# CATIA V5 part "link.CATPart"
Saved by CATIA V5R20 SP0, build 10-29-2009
Part number: link
Bounding box of the stored display mesh (mm): x -25 to 25, y -12.5 to 12.5, z -9.5 to 9.5
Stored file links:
  D:\Documents and Settings\mosavian\My Documents\DMU Project3\New Folder\link.CATPart
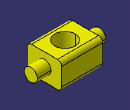
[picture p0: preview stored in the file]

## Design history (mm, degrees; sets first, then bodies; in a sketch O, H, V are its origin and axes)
Body1 (main body)
  Sketch1 on yz-plane, origin (0, 0, 0), H (0, 1, 0), V (0, 0, 1)
    circle A1 centre (0, 0) radius 4.75
    radius A1 = 4.75
  Pad1: profile Sketch1, direction (1, 0, 0), length 25, mirrored extent
  Sketch2 on yz-plane, origin (0, 0, 0), H (0, 1, 0), V (0, 0, 1)
    line L1 (12.5, 9.5) -> (12.5, -9.5)
    line L2 (12.5, -9.5) -> (-12.5, -9.5)
    line L3 (-12.5, -9.5) -> (-12.5, 9.5)
    line L4 (-12.5, 9.5) -> (12.5, 9.5)
    length L4 = 25
    length L1 = 19
    vertical: L1 V, L3 V
    horizontal: L2 H, L4 H
    equidistance: L1 L3 O, L2 L4 O
  Pad2: profile Sketch2, direction (1, 0, 0), length 15, mirrored extent
  Sketch3 on face of Pad2 from Sketch2.L4, origin (0, 0, 9.5), H (1, 0, 0), V (0, 1, 0)
    circle A1 centre (0, 0) radius 7.5
    radius A1 = 7.5
  Pocket1: profile Sketch3, direction (0, 0, -1), through (limit type 6)
  Fillet1: radius 3, on edge [face of Pad2 from Sketch2.L4 | face of Pad2 from Sketch2.L1]; edge [face of Pad2 from Sketch2.L3 | face of Pad2 from Sketch2.L4]; edge [face of Pad2 from Sketch2.L1 | face of Pad2 from Sketch2.L2]; edge [face of Pad2 from Sketch2.L2 | face of Pad2 from Sketch2.L3]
